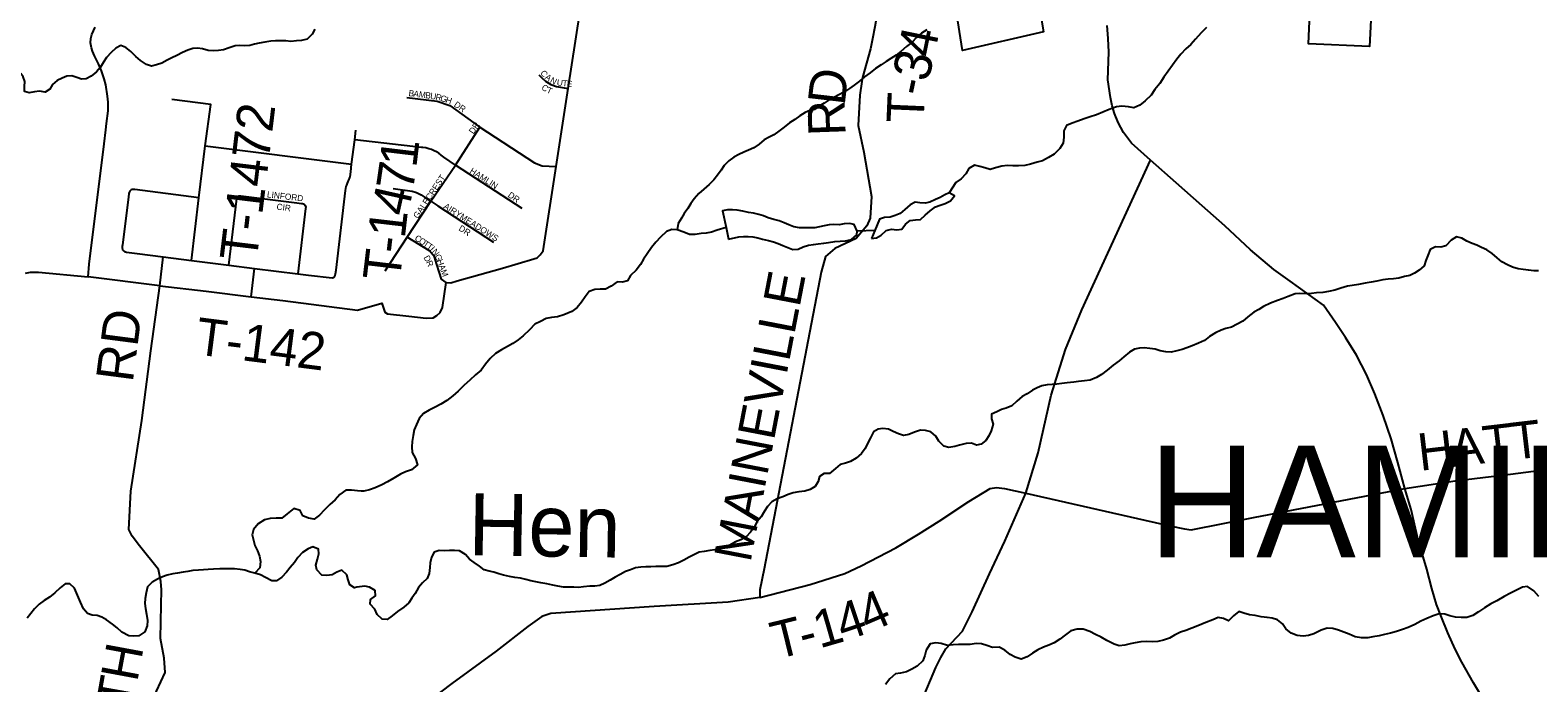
# Model space of a CAD drawing. Extents: x 1310247 to 1664935, y 284496 to 704931.
# Drawn here: x 1473471 to 1485632, y 476239 to 481504 of the extents above; entities that cross this region are included whole.
import ezdxf

# ---------------------------------------------------------------- set-up
doc = ezdxf.new("R2010")
doc.units = 0
for name, color, linetype in [('GM_P_State_Location', 7, 'Continuous'), ('GM_X_Airport_Location_Class_2', 7, 'Continuous'), ('GM_X_County_Road_Text', 7, 'Continuous'), ('GM_X_County_Subdivision_Text', 7, 'Continuous'), ('GM_X_Interstate_Shield', 7, 'Continuous'), ('GM_X_Major_Lake_Text', 7, 'Continuous'), ('GM_X_Minor_Lake_Text', 7, 'Continuous'), ('GM_X_Minor_River', 7, 'Continuous'), ('GM_X_Minor_River_Text', 7, 'Continuous'), ('GM_X_State_Location', 7, 'Continuous'), ('GM_X_Township_Road', 7, 'Continuous'), ('GM_X_Township_Subdivision', 7, 'Continuous')]:
    doc.layers.add(name, color=color, linetype=linetype)

msp = doc.modelspace()

# ---------------------------------------------------------------- linework, layer by layer
at = {"layer": 'GM_X_County_Road_Text'}
msp.add_lwpolyline([(1474456, 476098), (1474560, 476323), (1474552, 476438), (1474521, 476597), (1474528, 476867), (1474530, 476989), (1474526, 477058), (1474507, 477153), (1474353, 477344), (1474293, 477423), (1474267, 477477), (1474282, 477786), (1474373, 478355), (1474444, 478917), (1474516, 479443), (1473940, 479515), (1473948, 479617), (1474068, 480588), (1474082, 480701), (1474088, 480752), (1474099, 480854), (1474099, 480923), (1474094, 480971), (1474082, 481063), (1474069, 481111), (1474046, 481177), (1474021, 481232), (1473989, 481297), (1473973, 481335), (1473965, 481362), (1473958, 481401), (1473961, 481438), (1473969, 481468), (1473995, 481529)], dxfattribs=at)
at = {"layer": 'GM_X_County_Subdivision_Text'}
for points in [[(1480581, 482888), (1480559, 482405), (1480538, 482071), (1480518, 482022), (1480475, 481946), (1480342, 481721), (1480303, 481640), (1480285, 481532), (1480265, 481434)], [(1474516, 479443), (1474890, 479400), (1475254, 479353), (1475509, 479323), (1476111, 479245), (1476307, 479301), (1476333, 479229), (1476354, 479216), (1476525, 479196), (1476665, 479180), (1476721, 479183), (1476752, 479202), (1476779, 479228), (1476798, 479268), (1476827, 479470), (1476865, 479467), (1476916, 479482), (1477281, 479585), (1477534, 479659), (1477559, 479669), (1477584, 479691), (1477609, 479723), (1477714, 480404), (1477811, 481035), (1477934, 481834)], [(1480265, 481434), (1480262, 481421), (1480249, 481355), (1480184, 481122), (1480179, 481090)], [(1480179, 481090), (1480163, 480979), (1480150, 480736), (1480196, 480521), (1480258, 480163), (1480245, 479988), (1480218, 479926), (1480134, 479824), (1479960, 479742), (1479886, 479678), (1479851, 479551), (1479390, 477159), (1479357, 476991), (1479357, 476979)], [(1474772, 479647), (1474831, 480153), (1474883, 480572), (1474928, 480904), (1474614, 480946)], [(1474831, 480153), (1474314, 480218), (1474304, 480219), (1474294, 480218), (1474286, 480216), (1474279, 480211), (1474275, 480206), (1474272, 480201), (1474270, 480194), (1474268, 480186), (1474264, 480157), (1474216, 479772), (1474214, 479760), (1474213, 479748), (1474215, 479738), (1474217, 479733), (1474219, 479730), (1474224, 479724), (1474231, 479720), (1474239, 479716), (1474249, 479714), (1474335, 479703), (1474545, 479676), (1474772, 479647), (1475073, 479608), (1475281, 479582), (1475630, 479540), (1475717, 479529), (1475906, 479507), (1475914, 479508), (1475920, 479510), (1475923, 479512), (1475926, 479515), (1475929, 479519), (1475931, 479523), (1475932, 479527), (1475934, 479539), (1475938, 479568), (1476015, 480210), (1476017, 480226), (1476020, 480242), (1476024, 480253), (1476031, 480271), (1476045, 480301), (1476048, 480308), (1476050, 480315), (1476051, 480320), (1476051, 480321), (1476057, 480361), (1476064, 480423), (1476089, 480620), (1476097, 480698)], [(1474883, 480572), (1476064, 480423)], [(1479484, 472137), (1479515, 472304), (1479845, 473768), (1479878, 473896), (1480269, 474641), (1480342, 474834), (1480471, 475345), (1480660, 476090), (1480777, 476364), (1480816, 476444), (1480857, 476515), (1480990, 476656), (1481070, 476811), (1481210, 477120), (1481333, 477383), (1481503, 477769), (1481601, 478095), (1481705, 478561), (1481821, 478927), (1481954, 479248), (1482508, 480456)], [(1474516, 479443), (1474545, 479676)], [(1473433, 479543), (1473475, 479552), (1473537, 479552), (1473940, 479515)], [(1485597, 477946), (1485598, 477946), (1486175, 478013), (1486373, 478029), (1486429, 478036), (1486471, 478053), (1486995, 478349), (1487179, 478455)], [(1484559, 477808), (1484965, 477868), (1485410, 477922), (1485597, 477946)], [(1479357, 476929), (1479762, 477032), (1480043, 477121), (1480174, 477182), (1480454, 477328), (1480636, 477439), (1480802, 477543), (1481043, 477701), (1481214, 477808), (1481266, 477814), (1481329, 477808), (1481503, 477769), (1482663, 477506), (1482781, 477481), (1482835, 477473), (1483337, 477572), (1484559, 477808)], [(1479357, 476979), (1479357, 476929), (1479100, 476890), (1478504, 476854), (1477671, 476799), (1477597, 476775), (1477484, 476694), (1477229, 476496), (1476871, 476234), (1476305, 475804), (1475692, 475348), (1474181, 474175)]]:
    msp.add_lwpolyline(points, dxfattribs=at)
at = {"layer": 'GM_X_Interstate_Shield'}
msp.add_lwpolyline([(1485284, 475952), (1485113, 476240), (1485018, 476405), (1484964, 476510), (1484905, 476642), (1484854, 476768), (1484814, 476872), (1484777, 477001), (1484735, 477156), (1484667, 477390), (1484609, 477639), (1484559, 477808), (1484502, 478017), (1484449, 478209), (1484383, 478397), (1484318, 478570), (1484250, 478728), (1484168, 478882), (1484080, 479025), (1484000, 479146), (1483902, 479286), (1483635, 479480), (1483502, 479574), (1483315, 479732), (1483106, 479925), (1482923, 480086), (1482715, 480274), (1482508, 480456), (1482355, 480594), (1482289, 480678), (1482246, 480760), (1482216, 480831), (1482198, 480895), (1482185, 480960), (1482162, 481104), (1482170, 481328), (1482166, 481437), (1482157, 481541)], dxfattribs=at)
at = {"layer": 'GM_X_Major_Lake_Text'}
for points in [[(1484297, 481857), (1484274, 481373), (1483782, 481394), (1483806, 481948)], [(1481597, 481782), (1481643, 481490), (1480991, 481341), (1480937, 481683)]]:
    msp.add_lwpolyline(points, dxfattribs=at)
at = {"layer": 'GM_X_Minor_River'}
for points in [[(1480257, 479823), (1480298, 479830), (1480336, 479850), (1480375, 479887), (1480417, 479899), (1480462, 479894), (1480502, 479899), (1480531, 479939), (1480569, 479970), (1480611, 479974), (1480651, 479977), (1480690, 480011), (1480731, 480048), (1480774, 480078), (1480812, 480093), (1480852, 480106), (1480893, 480128), (1480927, 480167), (1480883, 480191)], [(1480883, 480191), (1480849, 480175), (1480811, 480155), (1480773, 480138), (1480728, 480118), (1480690, 480109), (1480648, 480112), (1480608, 480116), (1480569, 480095), (1480526, 480057), (1480488, 480026), (1480447, 480008), (1480407, 479997), (1480363, 479994), (1480321, 479980), (1480283, 479888)], [(1480142, 479882), (1480117, 479936), (1480079, 479946), (1480037, 479943), (1479995, 479935), (1479953, 479936), (1479915, 479935), (1479876, 479925), (1479838, 479918), (1479800, 479911), (1479756, 479909), (1479714, 479910), (1479675, 479910), (1479631, 479919), (1479590, 479934), (1479552, 479949), (1479512, 479965), (1479468, 479978), (1479424, 479991), (1479386, 480007), (1479348, 480018), (1479304, 480029), (1479264, 480033), (1479220, 480044), (1479174, 480053), (1479136, 480055), (1479096, 480054), (1479054, 480047), (1479084, 479912)], [(1479084, 479912), (1479104, 479819)], [(1479104, 479819), (1479187, 479838), (1479225, 479839), (1479263, 479841), (1479301, 479838), (1479339, 479830), (1479379, 479819), (1479425, 479808), (1479467, 479796), (1479505, 479783), (1479543, 479768), (1479583, 479752), (1479622, 479735), (1479665, 479738), (1479705, 479756), (1479749, 479771), (1479788, 479776), (1479828, 479780), (1479872, 479787), (1479910, 479792), (1479960, 479800), (1480005, 479801), (1480047, 479804), (1480097, 479816), (1480140, 479853), (1480142, 479882)], [(1480283, 479888), (1480257, 479823)]]:
    msp.add_lwpolyline(points, dxfattribs=at)
at = {"layer": 'GM_X_Minor_River_Text'}
for points in [[(1475766, 481511), (1475745, 481471), (1475706, 481432), (1475660, 481422), (1475618, 481417), (1475574, 481414), (1475532, 481418), (1475491, 481419), (1475451, 481418), (1475411, 481416), (1475363, 481407), (1475319, 481400), (1475280, 481392), (1475242, 481381), (1475200, 481379), (1475162, 481380), (1475124, 481377), (1475075, 481363), (1475031, 481346), (1474989, 481339), (1474950, 481337), (1474906, 481340), (1474860, 481353), (1474822, 481359), (1474784, 481356), (1474744, 481343), (1474699, 481325), (1474653, 481300), (1474614, 481280), (1474576, 481261), (1474534, 481238), (1474491, 481224), (1474449, 481215), (1474409, 481226), (1474361, 481260), (1474322, 481291), (1474282, 481332), (1474243, 481365), (1474203, 481381), (1474162, 481358), (1474124, 481324), (1474087, 481283), (1474062, 481245), (1474038, 481207), (1474005, 481168), (1473962, 481132), (1473924, 481113), (1473885, 481108), (1473848, 481122), (1473806, 481135), (1473767, 481134), (1473729, 481118), (1473689, 481097), (1473650, 481065), (1473629, 481027), (1473591, 481004), (1473547, 481011), (1473505, 481007)], [(1480703, 481508), (1480660, 481479), (1480620, 481444), (1480581, 481406), (1480540, 481373), (1480493, 481331), (1480455, 481302), (1480414, 481276), (1480374, 481251), (1480335, 481225), (1480288, 481194), (1480246, 481161), (1480201, 481127), (1480160, 481094), (1480118, 481060), (1480079, 481033), (1480039, 481008), (1479994, 480982), (1479954, 480961), (1479915, 480941), (1479875, 480916), (1479836, 480890), (1479798, 480865), (1479759, 480856), (1479721, 480840), (1479678, 480813), (1479638, 480783), (1479595, 480756), (1479552, 480721), (1479510, 480689), (1479469, 480660)], [(1482960, 481527), (1482915, 481483), (1482870, 481432), (1482833, 481388), (1482791, 481353), (1482752, 481311), (1482721, 481270), (1482686, 481222), (1482649, 481173), (1482614, 481125), (1482583, 481075), (1482543, 481026), (1482512, 480980), (1482465, 480935), (1482420, 480900), (1482374, 480878), (1482330, 480887), (1482277, 480890), (1482233, 480886), (1482175, 480865), (1482124, 480842), (1482072, 480821), (1482021, 480804), (1481973, 480788), (1481920, 480769), (1481876, 480754), (1481830, 480736), (1481807, 480693), (1481808, 480641), (1481803, 480594), (1481776, 480549), (1481731, 480505), (1481685, 480476), (1481636, 480449), (1481592, 480439), (1481540, 480422), (1481493, 480413), (1481443, 480410), (1481397, 480410), (1481355, 480413), (1481307, 480408), (1481258, 480395), (1481214, 480381), (1481172, 480394), (1481130, 480405), (1481088, 480415), (1481043, 480388), (1481019, 480346), (1480980, 480305), (1480937, 480275), (1480883, 480191)], [(1473505, 481007), (1473464, 480998), (1473424, 481009), (1473425, 481051), (1473428, 481089), (1473414, 481127), (1473395, 481156)], [(1479469, 480660), (1479431, 480640), (1479390, 480619), (1479350, 480585), (1479307, 480556), (1479266, 480535), (1479228, 480519), (1479186, 480502), (1479147, 480480), (1479107, 480449), (1479068, 480413), (1479045, 480376), (1479014, 480334), (1478984, 480296), (1478947, 480259), (1478904, 480222), (1478863, 480186), (1478827, 480143), (1478800, 480105), (1478775, 480067), (1478746, 480026), (1478724, 479988), (1478697, 479944), (1478690, 479894)], [(1479084, 479912), (1479011, 479891), (1478967, 479876), (1478924, 479868), (1478882, 479863), (1478834, 479856), (1478788, 479856), (1478744, 479875), (1478690, 479894), (1478646, 479897), (1478604, 479881), (1478555, 479834), (1478518, 479793), (1478483, 479751), (1478448, 479699), (1478417, 479656), (1478395, 479614), (1478358, 479569), (1478313, 479525), (1478290, 479483), (1478248, 479472), (1478206, 479473), (1478157, 479439), (1478112, 479414), (1478068, 479415), (1478026, 479413), (1477980, 479396), (1477947, 479354), (1477918, 479311), (1477883, 479267), (1477841, 479236), (1477776, 479207), (1477724, 479192), (1477675, 479186), (1477633, 479179), (1477587, 479154), (1477542, 479132), (1477499, 479087), (1477448, 479038), (1477406, 479006), (1477363, 478977), (1477320, 478953), (1477272, 478926), (1477225, 478897), (1477182, 478855), (1477144, 478810), (1477109, 478762), (1477062, 478723), (1477017, 478680), (1476972, 478640), (1476923, 478593), (1476879, 478555), (1476832, 478516), (1476783, 478487), (1476737, 478463), (1476690, 478440), (1476643, 478413), (1476609, 478371), (1476586, 478323), (1476569, 478280), (1476560, 478234), (1476553, 478186), (1476549, 478142), (1476552, 478097), (1476579, 478049), (1476596, 477998), (1476546, 477959), (1476499, 477942), (1476457, 477922), (1476404, 477891), (1476353, 477860), (1476307, 477837), (1476254, 477813), (1476208, 477796), (1476162, 477785), (1476141, 477786)], [(1480283, 479888), (1480142, 479882)], [(1485638, 479563), (1485598, 479564), (1485556, 479568), (1485514, 479575), (1485474, 479580), (1485426, 479592), (1485386, 479611), (1485342, 479636), (1485303, 479667), (1485263, 479703), (1485221, 479732), (1485178, 479751), (1485140, 479769), (1485102, 479784), (1485060, 479803), (1485018, 479826), (1484976, 479838), (1484932, 479809), (1484889, 479765), (1484849, 479754), (1484805, 479757), (1484762, 479735), (1484743, 479686), (1484728, 479646), (1484714, 479604), (1484675, 479568)], [(1484675, 479568), (1484636, 479545), (1484598, 479525), (1484556, 479518), (1484511, 479505), (1484467, 479499), (1484425, 479496), (1484381, 479489), (1484332, 479479), (1484286, 479472), (1484238, 479463), (1484186, 479454), (1484133, 479445), (1484095, 479439), (1484043, 479424), (1483994, 479407), (1483944, 479395), (1483896, 479388), (1483847, 479385), (1483805, 479380), (1483763, 479378), (1483713, 479379), (1483673, 479378), (1483618, 479356), (1483578, 479341), (1483531, 479324), (1483475, 479301), (1483418, 479275), (1483380, 479252), (1483341, 479229), (1483293, 479191), (1483252, 479156), (1483205, 479132), (1483161, 479109), (1483116, 479098), (1483076, 479084), (1483032, 479063), (1482983, 479032), (1482942, 479000), (1482894, 478979), (1482843, 478958), (1482801, 478942), (1482763, 478929), (1482720, 478918), (1482674, 478908), (1482630, 478909), (1482586, 478918), (1482546, 478930), (1482502, 478937), (1482456, 478942), (1482418, 478940), (1482379, 478931), (1482337, 478908), (1482292, 478870), (1482254, 478837), (1482205, 478801), (1482158, 478762), (1482113, 478727), (1482073, 478703), (1482022, 478682), (1481976, 478675), (1481926, 478670), (1481888, 478666), (1481835, 478659), (1481793, 478654), (1481753, 478648), (1481715, 478647), (1481675, 478643), (1481632, 478634), (1481594, 478619), (1481556, 478601), (1481513, 478572), (1481472, 478548), (1481430, 478511), (1481389, 478474), (1481344, 478456), (1481306, 478445), (1481268, 478425), (1481225, 478406), (1481225, 478368), (1481238, 478326), (1481223, 478272), (1481204, 478232), (1481180, 478194), (1481141, 478165), (1481103, 478157), (1481063, 478172), (1481021, 478171), (1480968, 478157), (1480928, 478146), (1480882, 478139), (1480840, 478149), (1480800, 478188), (1480777, 478229), (1480735, 478263), (1480693, 478274), (1480653, 478277), (1480605, 478261), (1480559, 478242), (1480516, 478235), (1480474, 478247)], [(1480474, 478247), (1480433, 478268), (1480393, 478287), (1480349, 478290), (1480311, 478286), (1480272, 478263), (1480249, 478217), (1480228, 478175), (1480206, 478131), (1480175, 478090), (1480132, 478052), (1480088, 478025), (1480047, 478012), (1480005, 478000), (1479966, 477969), (1479917, 477929), (1479875, 477928), (1479837, 477903), (1479828, 477863), (1479803, 477823), (1479761, 477798), (1479718, 477786), (1479672, 477779), (1479626, 477772), (1479584, 477758), (1479541, 477739), (1479497, 477724), (1479452, 477700), (1479417, 477661), (1479395, 477623), (1479366, 477579), (1479335, 477540), (1479310, 477496), (1479282, 477454), (1479247, 477417), (1479202, 477393), (1479160, 477376), (1479113, 477351), (1479075, 477333), (1479035, 477318), (1478994, 477313), (1478952, 477307), (1478906, 477300), (1478868, 477294), (1478829, 477275), (1478787, 477252), (1478744, 477230), (1478700, 477207), (1478655, 477192), (1478607, 477178), (1478565, 477177), (1478517, 477178), (1478477, 477176), (1478438, 477175), (1478396, 477172), (1478354, 477166), (1478312, 477151), (1478273, 477138), (1478229, 477114), (1478190, 477091), (1478150, 477067), (1478105, 477044), (1478067, 477025), (1478025, 477019), (1477986, 477020), (1477934, 477015), (1477894, 477009), (1477856, 477012), (1477816, 477012), (1477774, 477011), (1477726, 477020), (1477688, 477027), (1477638, 477037), (1477590, 477046), (1477550, 477055), (1477510, 477061), (1477470, 477072), (1477426, 477083), (1477380, 477090), (1477338, 477096), (1477290, 477109), (1477252, 477118), (1477210, 477132), (1477172, 477141), (1477134, 477152), (1477094, 477180), (1477053, 477209), (1477015, 477236), (1476982, 477274), (1476934, 477305), (1476894, 477306), (1476852, 477307), (1476812, 477305), (1476771, 477306), (1476729, 477294), (1476708, 477253), (1476698, 477207), (1476695, 477169), (1476690, 477121), (1476673, 477081), (1476635, 477045)], [(1476141, 477786), (1476111, 477788), (1476063, 477794), (1476017, 477793), (1475969, 477758), (1475930, 477716), (1475887, 477677), (1475846, 477635), (1475805, 477592), (1475763, 477559), (1475715, 477569), (1475671, 477586), (1475649, 477629), (1475598, 477647), (1475545, 477604), (1475500, 477569), (1475454, 477567), (1475406, 477564), (1475361, 477553), (1475311, 477522), (1475272, 477476), (1475261, 477434), (1475272, 477390), (1475282, 477348), (1475305, 477305), (1475320, 477261), (1475328, 477217)], [(1476105, 477010), (1476086, 477006), (1476049, 477031), (1476035, 477071), (1476024, 477111), (1475984, 477148), (1475944, 477133), (1475906, 477111), (1475865, 477104), (1475823, 477108), (1475784, 477151), (1475776, 477189), (1475789, 477237), (1475798, 477279), (1475797, 477317), (1475751, 477336), (1475712, 477321), (1475668, 477291), (1475631, 477250), (1475602, 477210), (1475568, 477169), (1475539, 477131), (1475502, 477091), (1475459, 477062), (1475421, 477063), (1475370, 477088), (1475328, 477110), (1475284, 477123), (1475240, 477136), (1475202, 477148), (1475164, 477153), (1475118, 477158), (1475078, 477160), (1475038, 477159), (1475000, 477160), (1474951, 477156), (1474907, 477155), (1474869, 477152), (1474829, 477148), (1474783, 477145), (1474744, 477138), (1474704, 477132), (1474660, 477125), (1474622, 477118), (1474577, 477108), (1474539, 477095), (1474499, 477077), (1474454, 477052), (1474417, 477014), (1474407, 476965), (1474398, 476919), (1474395, 476879), (1474400, 476838), (1474410, 476794), (1474417, 476742), (1474416, 476698), (1474397, 476650), (1474347, 476619), (1474306, 476615), (1474266, 476618), (1474211, 476649), (1474173, 476682), (1474136, 476712), (1474088, 476747), (1474050, 476768), (1474012, 476782), (1473972, 476785), (1473934, 476798), (1473901, 476836), (1473878, 476889), (1473862, 476927), (1473845, 476965), (1473829, 477004), (1473792, 477037), (1473754, 477037), (1473713, 477006), (1473670, 476966), (1473626, 476931), (1473585, 476903), (1473544, 476874), (1473506, 476837), (1473477, 476799), (1473446, 476761)], [(1475328, 477217), (1475323, 477168), (1475284, 477123)], [(1476635, 477045), (1476604, 477008), (1476575, 476960), (1476550, 476922), (1476524, 476885), (1476485, 476849), (1476434, 476814), (1476392, 476779), (1476351, 476751), (1476309, 476752), (1476269, 476790), (1476252, 476833), (1476213, 476874), (1476217, 476912), (1476256, 476941), (1476253, 476983), (1476209, 477012), (1476171, 477019), (1476127, 477015), (1476105, 477010)], [(1485640, 476936), (1485599, 476981), (1485549, 477016), (1485507, 477010), (1485455, 476985), (1485412, 476962), (1485359, 476935), (1485301, 476901), (1485252, 476876), (1485201, 476845), (1485153, 476812), (1485106, 476782), (1485060, 476767), (1485014, 476766), (1484968, 476770), (1484922, 476781), (1484880, 476794), (1484836, 476797), (1484787, 476781), (1484735, 476758), (1484688, 476737), (1484638, 476709), (1484585, 476686), (1484541, 476669), (1484492, 476654), (1484442, 476640), (1484395, 476629), (1484353, 476618), (1484301, 476611), (1484259, 476603), (1484208, 476602), (1484158, 476611), (1484111, 476632), (1484067, 476648), (1484023, 476665)], [(1484023, 476665), (1483977, 476678), (1483931, 476681), (1483884, 476665), (1483826, 476634), (1483781, 476621), (1483739, 476617), (1483689, 476622), (1483643, 476639), (1483600, 476674), (1483572, 476716), (1483531, 476749), (1483489, 476762), (1483447, 476766), (1483401, 476773), (1483351, 476782), (1483305, 476789), (1483261, 476802), (1483219, 476816), (1483176, 476781), (1483137, 476739), (1483096, 476758), (1483054, 476767), (1483011, 476749), (1482953, 476726), (1482890, 476699), (1482840, 476680), (1482791, 476661), (1482749, 476649), (1482702, 476624), (1482660, 476601), (1482613, 476585), (1482567, 476572), (1482521, 476571), (1482473, 476573), (1482430, 476570), (1482384, 476561), (1482342, 476553), (1482300, 476542), (1482255, 476537), (1482214, 476551), (1482156, 476580), (1482110, 476609), (1482064, 476630), (1482017, 476653), (1481965, 476672), (1481917, 476672), (1481866, 476659), (1481822, 476626), (1481775, 476591), (1481730, 476563), (1481688, 476544), (1481643, 476526), (1481599, 476505), (1481556, 476480), (1481512, 476448), (1481465, 476431), (1481417, 476446), (1481376, 476469), (1481332, 476503), (1481286, 476528), (1481234, 476525), (1481188, 476540), (1481144, 476554), (1481100, 476557), (1481052, 476550), (1481010, 476549), (1480960, 476549), (1480915, 476546), (1480869, 476541), (1480819, 476556), (1480777, 476562), (1480731, 476553), (1480698, 476503), (1480687, 476459), (1480671, 476418), (1480626, 476374), (1480583, 476351), (1480539, 476327), (1480492, 476318), (1480450, 476313), (1480405, 476273), (1480370, 476226)]]:
    msp.add_lwpolyline(points, dxfattribs=at)
at = {"layer": 'GM_X_State_Location'}
for points in [[(1477575, 481143), (1477600, 481116), (1477627, 481094), (1477670, 481066), (1477716, 481050), (1477811, 481035)], [(1476508, 480960), (1476754, 480932), (1476856, 480897), (1477099, 480722), (1477540, 480434), (1477601, 480409), (1477714, 480404)], [(1476334, 479564), (1476512, 479834), (1476703, 480126), (1476901, 480415), (1477099, 480722)], [(1477439, 480067), (1476901, 480415), (1476807, 480479), (1476787, 480496), (1476766, 480511), (1476748, 480522), (1476729, 480531), (1476707, 480541), (1476686, 480548), (1476662, 480554), (1476638, 480557), (1476628, 480558), (1476089, 480620)], [(1476398, 480228), (1476551, 480205), (1476588, 480196), (1476624, 480176), (1476661, 480152), (1476703, 480126), (1476760, 480086), (1477207, 479793)], [(1475073, 479608), (1475130, 480078), (1475136, 480125), (1475139, 480146), (1475141, 480154), (1475145, 480160), (1475149, 480164), (1475155, 480167), (1475162, 480168), (1475170, 480168), (1475622, 480112), (1475642, 480110), (1475660, 480107), (1475660, 480107), (1475668, 480106), (1475675, 480104), (1475680, 480101), (1475685, 480097), (1475690, 480091), (1475693, 480084), (1475694, 480076), (1475693, 480067), (1475630, 479540)], [(1476827, 479470), (1476789, 479497), (1476752, 479615), (1476731, 479675), (1476691, 479724), (1476512, 479834)], [(1475254, 479353), (1475281, 479582)]]:
    msp.add_lwpolyline(points, dxfattribs=at)

# ---------------------------------------------------------------- texts
at = {"layer": 'GM_P_State_Location'}
for s, rotation, p in [('C', 307.0059, (1477582, 481158)), ('A', 324.0892, (1477618, 481115)), ('N', 332.4881, (1477660, 481085)), ('U', 351.2161, (1477716, 481060)), ('T', 353.5496, (1477762, 481053)), ('E', 353.6625, (1477797, 481049)), ('B', 352.7469, (1476521, 480973)), ('A', 352.7469, (1476560, 480968)), ('M', 352.7469, (1476604, 480963)), ('B', 352.7469, (1476656, 480956)), ('U', 350.7598, (1476695, 480951)), ('R', 346.7856, (1476737, 480944)), ('G', 342.8114, (1476775, 480935)), ('H', 340.8243, (1476817, 480922)), ('C', 324.8548, (1477590, 481031)), ('T', 335.1364, (1477631, 481003)), ('DR', 325.5013, (1476884, 480893)), ('DR', 56.3032, (1477047, 480662)), ('HAMLIN', 327.4461, (1477011, 480356)), ('GALECREST', 56.1128, (1476598, 479980)), ('LINFORD', 353.3458, (1475379, 480156)), ('CIR', 352.5641, (1475456, 480057)), ('AIRYMEADOWS', 327.3631, (1476800, 480071)), ('DR', 325.495, (1477319, 480163)), ('DR', 327.9873, (1476922, 479893)), ('C', 326.1281, (1476567, 479815)), ('O', 326.1038, (1476600, 479793)), ('T', 326.1116, (1476636, 479769)), ('T', 326.1205, (1476665, 479749)), ('I', 312.8354, (1476692, 479732)), ('N', 307.7005, (1476707, 479716)), ('D', 298.1586, (1476642, 479671)), ('R', 291.7924, (1476663, 479634)), ('G', 293.6319, (1476732, 479684)), ('H', 290.5228, (1476749, 479645)), ('A', 290.3565, (1476765, 479603)), ('M', 290.3499, (1476780, 479562))]:
    msp.add_text(s, height=50, rotation=rotation, dxfattribs=at).set_placement(p)
at = {"layer": 'GM_X_Airport_Location_Class_2'}
msp.add_text('HAMILTON', height=900, rotation=0, dxfattribs=at).set_placement((1482491, 477253))
at = {"layer": 'GM_X_Minor_Lake_Text'}
msp.add_text('Hen', height=500, rotation=359.0831, dxfattribs=at).set_placement((1477003, 477269))
at = {"layer": 'GM_X_Township_Road'}
for s, rotation, p in [('RD', 82.5687, (1474298, 478657)), ('H', 79.4638, (1474334, 476240)), ('T', 79.9761, (1474295, 476020))]:
    msp.add_text(s, height=300, rotation=rotation, dxfattribs=at).set_placement(p)
at = {"layer": 'GM_X_Township_Subdivision'}
for s, rotation, p in [('4', 78.384, (1480760, 481273)), ('3', 75.3807, (1480710, 481078)), ('D', 83.447, (1480040, 480890)), ('-', 78.041, (1480685, 480961)), ('T', 87.5307, (1480677, 480750)), ('T-1472', 83.1093, (1475297, 479633)), ('R', 92.0612, (1480049, 480656)), ('1', 83.1807, (1476585, 480389)), ('7', 81.6972, (1476557, 480198)), ('4', 77.3459, (1476512, 479993)), ('1', 83.4022, (1476492, 479818)), ('T', 83.2258, (1476451, 479472)), ('-', 83.2423, (1476477, 479695)), ('MAINEVILLE', 79.1061, (1479280, 477203)), ('T-142', 352.7007, (1474794, 478891)), ('H', 6.7071, (1484681, 477949)), ('A', 6.708, (1484943, 477980)), ('T', 6.7051, (1485205, 478010)), ('T', 6.7051, (1485428, 478037)), ('4', 23.1731, (1480229, 476639)), ('1', 16.054, (1479838, 476516)), ('4', 18.5577, (1480029, 476571)), ('T', 13.7951, (1479488, 476428)), ('-', 14.3055, (1479709, 476483))]:
    msp.add_text(s, height=300, rotation=rotation, dxfattribs=at).set_placement(p)

doc.saveas('drawing.dxf')
